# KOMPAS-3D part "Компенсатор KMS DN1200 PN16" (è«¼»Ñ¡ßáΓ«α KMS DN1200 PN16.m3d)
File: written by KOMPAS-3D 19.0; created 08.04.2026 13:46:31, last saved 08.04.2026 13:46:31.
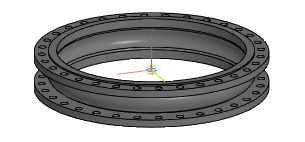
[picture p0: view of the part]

Document properties: Автор: Энергия; Полное имя файла: Z:\3.Личные\kachalov\3d для проектировщиков\7.1 Компенсатор\stp_Компенсатор KSM\Компенсатор KMS DN1200 PN16.m3d

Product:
- Part/product: Компенсатор KMS DN1200 PN16

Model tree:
1. Операция без истории:1  (labels: Компенсатор KMS DN1200 PN16)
